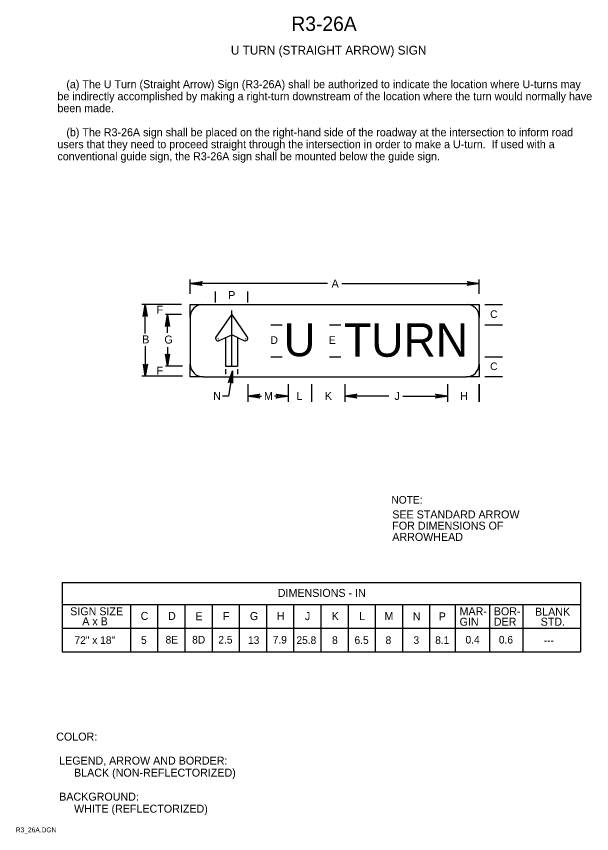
# Model space of a CAD drawing. Extents: x 0.5 to 7.6, y 0.2 to 10.2.
import ezdxf

# ---------------------------------------------------------------- set-up
doc = ezdxf.new("R2010")
doc.units = 0
for name, color, linetype in [('1', 7, 'Continuous'), ('11', 7, 'Continuous'), ('12', 7, 'Continuous'), ('2', 7, 'Continuous'), ('3', 7, 'Continuous')]:
    doc.layers.add(name, color=color, linetype=linetype)

# ---------------------------------------------------------------- blocks, each defined once
blk = doc.blocks.new('RARROW')
at = {"layer": '3'}
for p, q in [((-84.9, 11.2), (-89.2, 15.1)), ((-89.2, 15.1), (0, 0)), ((0, 0), (-89.2, -14.9)), ((-84.9, 11.2), (-81.7, 4.8)), ((0, 0), (-84.9, 11.2)), ((-84.6, -10.6), (0, 0)), ((-81.7, 4.8), (0, 0)), ((0, 0), (-81.7, -4.3)), ((-89.2, -14.9), (-84.6, -10.6)), ((-81.7, -4.3), (-84.6, -10.6))]:
    blk.add_line(p, q, dxfattribs=at)

msp = doc.modelspace()

# ---------------------------------------------------------------- linework, layer by layer
at = {"layer": '11'}
for p, q in [((2.638, 6.502), (2.638, 6.66)), ((2.638, 6.66), (2.796, 6.66)), ((6.032, 6.66), (6.19, 6.66)), ((6.19, 6.66), (6.19, 6.502)), ((2.638, 5.772), (2.638, 5.929)), ((6.19, 5.929), (6.19, 5.772)), ((2.796, 5.772), (2.638, 5.772)), ((6.19, 5.772), (6.032, 5.772))]:
    msp.add_line(p, q, dxfattribs=at)
at = {"layer": '12'}
for p, q in [((3.147, 6.544), (2.954, 6.259)), ((3.341, 6.258), (3.147, 6.544)), ((2.994, 6.218), (3.068, 6.251)), ((3.226, 6.251), (3.298, 6.22))]:
    msp.add_line(p, q, dxfattribs=at)
for centre, major_axis, start_param, end_param in [((2.981, 6.244), (-0.032, 0), 5.722676, 8.270867), ((3.313, 6.244), (-0.0318, 0), 1.068412, 3.650841)]:
    msp.add_ellipse(centre, major_axis=major_axis, ratio=0.881834, start_param=start_param, end_param=end_param, dxfattribs=at)
at = {"layer": '3'}
for p, q in [((2.638, 6.792), (2.638, 6.969)), ((6.19, 6.792), (6.19, 6.969)), ((4.327, 6.919), (2.638, 6.919)), ((4.501, 6.919), (6.19, 6.919)), ((2.949, 6.686), (2.949, 6.823)), ((3.345, 6.686), (3.345, 6.823)), ((2.528, 6.662), (2.043, 6.662)), ((2.085, 6.304), (2.085, 6.662)), ((2.786, 6.66), (6.042, 6.66)), ((6.26, 6.66), (6.477, 6.66)), ((2.528, 6.539), (2.333, 6.539)), ((2.359, 6.314), (2.359, 6.539)), ((3.148, 5.9), (3.148, 6.589)), ((2.638, 6.512), (2.638, 5.929)), ((6.19, 5.929), (6.19, 6.512)), ((3.63, 6.413), (3.769, 6.413)), ((4.349, 6.413), (4.488, 6.413)), ((6.26, 6.413), (6.477, 6.413)), ((3.068, 6.251), (3.148, 6.288)), ((3.072, 6.253), (3.072, 5.904)), ((3.226, 6.251), (3.148, 6.288)), ((3.22, 6.254), (3.22, 5.904)), ((2.085, 6.148), (2.085, 5.781)), ((2.359, 6.135), (2.359, 5.905)), ((3.63, 6.018), (3.769, 6.018)), ((4.349, 6.018), (4.488, 6.018)), ((6.26, 6.018), (6.477, 6.018)), ((2.543, 5.904), (2.333, 5.904)), ((3.072, 5.904), (3.22, 5.904)), ((3.072, 5.867), (3.072, 5.805)), ((3.158, 5.844), (3.106, 5.536)), ((3.22, 5.867), (3.22, 5.805)), ((2.543, 5.781), (2.041, 5.781)), ((2.796, 5.772), (6.032, 5.772)), ((6.477, 5.772), (6.26, 5.772)), ((3.345, 5.682), (3.345, 5.465)), ((3.84, 5.682), (3.84, 5.465)), ((4.13, 5.682), (4.13, 5.465)), ((4.539, 5.682), (4.539, 5.465)), ((5.802, 5.682), (5.802, 5.465)), ((6.19, 5.682), (6.19, 5.465)), ((6.19, 5.465), (6.19, 5.682)), ((3.106, 5.536), (3.034, 5.536)), ((3.346, 5.536), (3.512, 5.536)), ((3.84, 5.536), (3.672, 5.536)), ((5.079, 5.536), (4.539, 5.536)), ((5.251, 5.536), (5.802, 5.536)), ((5.73, 5.536), (5.708, 5.536)), ((1.063, 3.243), (1.063, 2.392)), ((1.063, 3.243), (7.439, 3.243)), ((7.439, 3.243), (7.439, 2.392)), ((1.063, 2.972), (7.439, 2.972)), ((1.901, 2.972), (1.901, 2.392)), ((2.236, 2.972), (2.236, 2.392)), ((2.57, 2.972), (2.57, 2.392)), ((2.905, 2.972), (2.905, 2.392)), ((3.24, 2.972), (3.24, 2.392)), ((3.574, 2.972), (3.574, 2.392)), ((3.909, 2.972), (3.909, 2.392)), ((4.244, 2.972), (4.244, 2.392)), ((4.578, 2.972), (4.578, 2.392)), ((4.913, 2.972), (4.913, 2.392)), ((5.248, 2.972), (5.248, 2.392)), ((5.582, 2.972), (5.582, 2.392)), ((5.896, 2.972), (5.896, 2.392)), ((6.317, 2.972), (6.317, 2.392)), ((6.726, 2.972), (6.726, 2.392)), ((1.063, 2.682), (7.439, 2.682)), ((1.063, 2.392), (7.439, 2.392))]:
    msp.add_line(p, q, dxfattribs=at)
for centre, radius, start, end in [((2.786, 6.512), 0.148, 90, 180), ((6.042, 6.512), 0.148, 0, 90), ((2.796, 5.929), 0.158, 180, 270), ((6.032, 5.929), 0.158, 270, 0)]:
    msp.add_arc(centre, radius, start, end, dxfattribs=at)

# ---------------------------------------------------------------- block references
at = {"layer": '3', "xscale": 0.0016545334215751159, "yscale": 0.0016366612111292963}
for p, rotation in [((2.638, 6.919), 180), ((2.085, 6.662), 90), ((2.359, 6.539), 90), ((2.359, 5.905), -90), ((2.085, 5.781), -90), ((3.158, 5.844), 80.39801742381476), ((3.346, 5.536), 180), ((4.539, 5.536), 180)]:
    msp.add_blockref('RARROW', p, dxfattribs=dict(at, rotation=rotation))
for p in [(6.19, 6.919), (3.84, 5.536), (5.802, 5.536)]:
    msp.add_blockref('RARROW', p, dxfattribs=at)

# ---------------------------------------------------------------- texts
at = {"layer": '1'}
for s, height, p in [('R3-26A', 0.1772, (3.881, 10.025)), ('U TURN (STRAIGHT ARROW) SIGN', 0.10828, (3.137, 9.734)), ('NOTE:', 0.0935, (5.112, 4.213)), ('SEE STANDARD ARROW', 0.09842, (5.122, 4.031)), ('FOR DIMENSIONS OF', 0.09842, (5.122, 3.893)), ('ARROWHEAD', 0.0984, (5.122, 3.755)), ('COLOR:', 0.0984, (0.989, 1.299)), (' LEGEND, ARROW AND BORDER:', 0.09842, (0.989, 1.004)), ('      BLACK (NON-REFLECTORIZED)', 0.09842, (0.989, 0.856)), (' BACKGROUND:', 0.09842, (0.989, 0.561)), ('      WHITE (REFLECTORIZED)', 0.09842, (0.989, 0.413)), ('R3_26A.DGN', 0.0591, (0.492, 0.172))]:
    msp.add_text(s, height=height, dxfattribs=at).set_placement(p)
at = {"layer": '12'}
for s, height, p in [('U', 0.403, (3.787, 6.025)), ('TURN', 0.4114, (4.527, 6.019))]:
    msp.add_text(s, height=height, dxfattribs=at).set_placement(p)
msp.add_text('+', height=0.0352, rotation=89.8926, dxfattribs=at).set_placement((2.997, 6.224))
at = {"layer": '2'}
for s, height, p in [('   (a) The U Turn (Straight Arrow) Sign (R3-26A) shall be authorized to indicate the location where U-turns may ', 0.098415, (1.004, 9.321)), ('be indirectly accomplished by making a right-turn downstream of the location where the turn would normally have ', 0.098415, (1.004, 9.173)), ('been made.', 0.0984, (1.004, 9.026)), ('   (b) The R3-26A sign shall be placed on the right-hand side of the roadway at the intersection to inform road ', 0.098415, (1.004, 8.73)), ('users that they need to proceed straight through the intersection in order to make a U-turn.  If used with a ', 0.098415, (1.004, 8.583)), ('conventional guide sign, the R3-26A sign shall be mounted below the guide sign.', 0.09842, (1.004, 8.435))]:
    msp.add_text(s, height=height, dxfattribs=at).set_placement(p)
at = {"layer": '3'}
for s, height, p in [('A', 0.0984, (4.376, 6.87)), ('P', 0.0984, (3.105, 6.728)), ('F', 0.0984, (2.223, 6.549)), ('C', 0.0935, (6.326, 6.496)), ('B', 0.0984, (2.047, 6.183)), ('G', 0.0984, (2.32, 6.181)), ('D', 0.0935, (3.625, 6.177)), ('E', 0.0935, (4.343, 6.177)), ('C', 0.0935, (6.326, 5.855)), ('F', 0.0984, (2.223, 5.799)), ('N', 0.0984, (2.919, 5.488)), ('M', 0.0984, (3.544, 5.488)), ('L', 0.0984, (3.944, 5.488)), ('K', 0.0984, (4.293, 5.488)), ('J', 0.0984, (5.149, 5.488)), ('H', 0.0984, (5.957, 5.488)), ('DIMENSIONS - IN', 0.09842, (3.714, 3.066)), ('SIGN SIZE', 0.0984, (1.161, 2.84)), ('MAR-', 0.0984, (5.95, 2.84)), ('BOR-', 0.0984, (6.371, 2.84)), ('BLANK', 0.0984, (6.878, 2.835)), ('A x B', 0.0984, (1.309, 2.717)), ('C', 0.0984, (2.028, 2.783)), ('D', 0.0984, (2.364, 2.783)), ('E', 0.0984, (2.701, 2.779)), ('F', 0.0984, (3.039, 2.781)), ('G', 0.0984, (3.371, 2.781)), ('H', 0.0984, (3.701, 2.781)), ('J', 0.0984, (4.048, 2.781)), ('K', 0.0984, (4.377, 2.781)), ('L', 0.0984, (4.714, 2.781)), ('M', 0.0984, (5.026, 2.781)), ('N', 0.0984, (5.375, 2.777)), ('P', 0.0984, (5.693, 2.777)), ('GIN', 0.0984, (5.95, 2.712)), ('DER', 0.0984, (6.371, 2.712)), ('STD.', 0.0984, (6.947, 2.712)), ('72" x 18"', 0.0935, (1.214, 2.488)), ('5', 0.0935, (2.032, 2.488)), ('8E', 0.0935, (2.334, 2.493)), ('8D', 0.0935, (2.661, 2.493)), ('2.5', 0.0935, (2.983, 2.493)), ('13', 0.0935, (3.348, 2.488)), ('7.9', 0.0935, (3.652, 2.493)), ('25.8', 0.0935, (3.944, 2.488)), ('8', 0.0935, (4.382, 2.488)), ('6.5', 0.0935, (4.658, 2.488)), ('8', 0.0935, (5.04, 2.488)), ('3', 0.0935, (5.383, 2.488)), ('8.1', 0.0935, (5.65, 2.488)), ('0.4', 0.0935, (6.023, 2.493)), ('0.6', 0.0935, (6.433, 2.493)), ('---', 0.0935, (6.985, 2.485))]:
    msp.add_text(s, height=height, dxfattribs=at).set_placement(p)
msp.add_text('+', height=0.0352, rotation=90.0163, dxfattribs=at).set_placement((3.335, 6.224))

doc.saveas('drawing.dxf')
